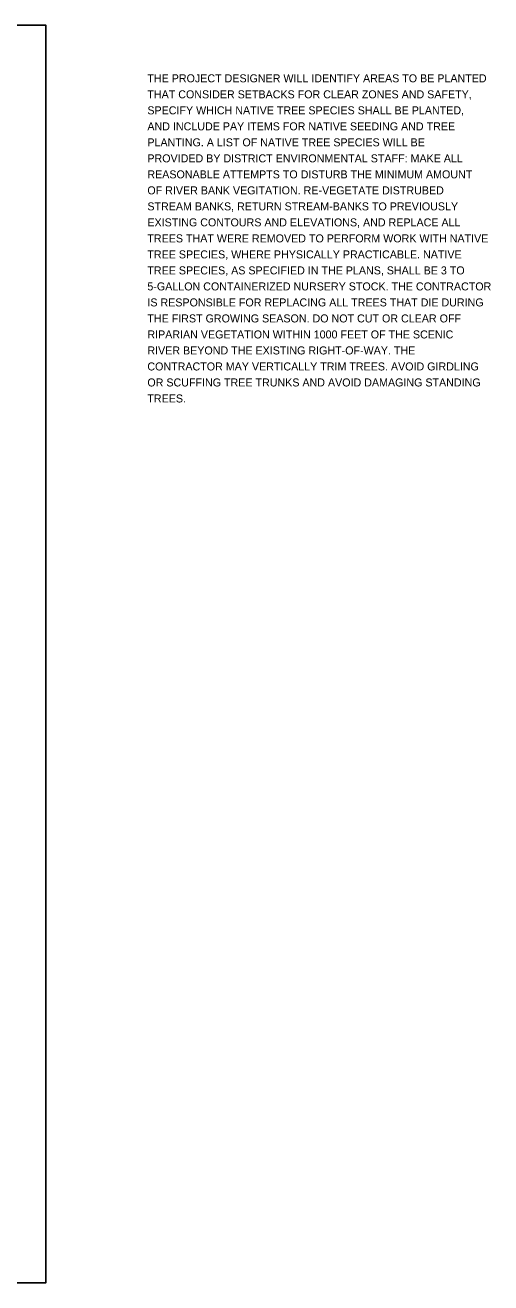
# Model space of a CAD drawing. Extents: x 0 to 41.8, y 0 to 22.
# Drawn here: x 33.64 to 41.79, y 0 to 22 of the extents above; entities that cross this region are included whole.
import ezdxf

# ---------------------------------------------------------------- set-up
doc = ezdxf.new("R2010")
doc.units = 0
doc.layers.add('SH_Cut_Line', color=7, linetype='Continuous')
doc.layers.add('SH_Text', color=7, linetype='Continuous')

msp = doc.modelspace()

# ---------------------------------------------------------------- linework, layer by layer
at = {"layer": 'SH_Cut_Line'}
msp.add_lwpolyline([(0, 0), (34, 0), (34, 22), (0, 22)], close=True, dxfattribs=at)

# ---------------------------------------------------------------- texts
at = {"layer": 'SH_Text'}
for s, p in [('THE PROJECT DESIGNER WILL IDENTIFY AREAS TO BE PLANTED ', (35.778, 21)), ('THAT CONSIDER SETBACKS FOR CLEAR ZONES AND SAFETY, ', (35.778, 20.72)), ('SPECIFY WHICH NATIVE TREE SPECIES SHALL BE PLANTED, ', (35.778, 20.44)), ('AND INCLUDE PAY ITEMS FOR NATIVE SEEDING AND TREE ', (35.778, 20.16)), ('PLANTING. A LIST OF NATIVE TREE SPECIES WILL BE ', (35.778, 19.88)), ('PROVIDED BY DISTRICT ENVIRONMENTAL STAFF: MAKE ALL ', (35.778, 19.6)), ('REASONABLE ATTEMPTS TO DISTURB THE MINIMUM AMOUNT ', (35.778, 19.32)), ('OF RIVER BANK VEGITATION. RE-VEGETATE DISTRUBED ', (35.778, 19.04)), ('STREAM BANKS, RETURN STREAM-BANKS TO PREVIOUSLY ', (35.778, 18.76)), ('EXISTING CONTOURS AND ELEVATIONS, AND REPLACE ALL ', (35.778, 18.48)), ('TREES THAT WERE REMOVED TO PERFORM WORK WITH NATIVE ', (35.778, 18.2)), ('TREE SPECIES, WHERE PHYSICALLY PRACTICABLE. NATIVE ', (35.778, 17.92)), ('TREE SPECIES, AS SPECIFIED IN THE PLANS, SHALL BE 3 TO ', (35.778, 17.64)), ('5-GALLON CONTAINERIZED NURSERY STOCK. THE CONTRACTOR ', (35.778, 17.36)), ('IS RESPONSIBLE FOR REPLACING ALL TREES THAT DIE DURING ', (35.778, 17.08)), ('THE FIRST GROWING SEASON. DO NOT CUT OR CLEAR OFF ', (35.778, 16.8)), ('RIPARIAN VEGETATION WITHIN 1000 FEET OF THE SCENIC ', (35.778, 16.52)), ('RIVER BEYOND THE EXISTING RIGHT-OF-WAY. THE ', (35.778, 16.24)), ('CONTRACTOR MAY VERTICALLY TRIM TREES. AVOID GIRDLING ', (35.778, 15.96)), ('OR SCUFFING TREE TRUNKS AND AVOID DAMAGING STANDING ', (35.778, 15.68)), ('TREES. ', (35.778, 15.4))]:
    msp.add_text(s, height=0.14, dxfattribs=at).set_placement(p)

doc.saveas('drawing.dxf')
